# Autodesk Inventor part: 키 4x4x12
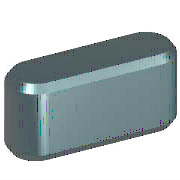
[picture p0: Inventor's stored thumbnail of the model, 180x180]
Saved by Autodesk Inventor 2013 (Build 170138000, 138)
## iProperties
IsCustomPart: 1
Created: 2012-02
Part Number: 키 4x4x12
Material: 강철, 연강
Description: 키 및 해당 키홈
Document SubType Name: Modeling
Standard: KS B 1311
Designer: mduedu
Standards Organization: KS
Language: ko-KR
Size Designation: 4 x 4 x 12
Categories: <MemberInstance><Categories><Category DisplayName="샤프트 부품" InternalName="7f7aeb1f-a693-4053-b835-cee3144e0d98" Mnemonic="SHFT"><Category DisplayName="키" Interna
Density: 7.86 g/cm^3
Mass: 1.38739 g
Surface Area: 1.94869 cm^2
Volume: 0.176513 cm^3
Author: mduedu
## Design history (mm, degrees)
workplane "Work Plane1"
workplane "Work Plane2"
sketch "스케치1"
  geometry: L1 (2, 2)-(10, 2); L2 (10, -2)-(2, -2); L3 (0, 9.4)-(0, -7.4) reference; L4 (-5, 0)-(30, 0) reference; L5 (12, 0)-(12, 7); A1 r 2 centre (2, 0) between (2, 2) and (2, -2); A2 r 2 centre (10, 0) between (10, -2) and (10, 2)
  constraints: 6 end point, 5 point on circle, 4 tangent, 3 point on line, 2 centre point, 1 horizontal, 1 parallel, 1 perpendicular
  dimensions: "d0" = 2 radius of A1 (= 0.5 x PB); "d13" = 2 radius of A2 (= 0.5 x PB); "d14" = 12 distance between parallel lines of L5 L3 (= NLG)
extrude "본체1" new body sketch "스케치1" taper "d3" = 0 deg; stored distance "d4" = 10
workplane "Work Plane3"
body "Solid1"
chamfer "모따기1" distance "d8" = 0.25 (= PHH); stored, may be unused: second distance "d9" = 0.25 (= PHH), angle "d15" = 45 deg
other parameters: "d1" = -2.5 (= -PNT), "d2" = 1.5 (= PH - PNT), "NLG" = 12 [user parameter; used in 3 equation terms], "PB" = 4 [user parameter; used in 2 equation terms], "PNT" = 2.5 [user parameter; used in 2 equation terms], "PH" = 4 [user parameter; used in 1 equation term], "PHH" = 0.25 [user parameter; used in 2 equation terms], "d10" = 0, "d16" = 0, "d17" = 0, "d18" = 0, "PLB2" = 12 (= NLG) [user parameter], "WDMAX" = 12 [user parameter], "PLB1" = 12 (= NLG) [user parameter], "RR" = 0.08 [user parameter], "PUEB" = 1.8 [user parameter]
